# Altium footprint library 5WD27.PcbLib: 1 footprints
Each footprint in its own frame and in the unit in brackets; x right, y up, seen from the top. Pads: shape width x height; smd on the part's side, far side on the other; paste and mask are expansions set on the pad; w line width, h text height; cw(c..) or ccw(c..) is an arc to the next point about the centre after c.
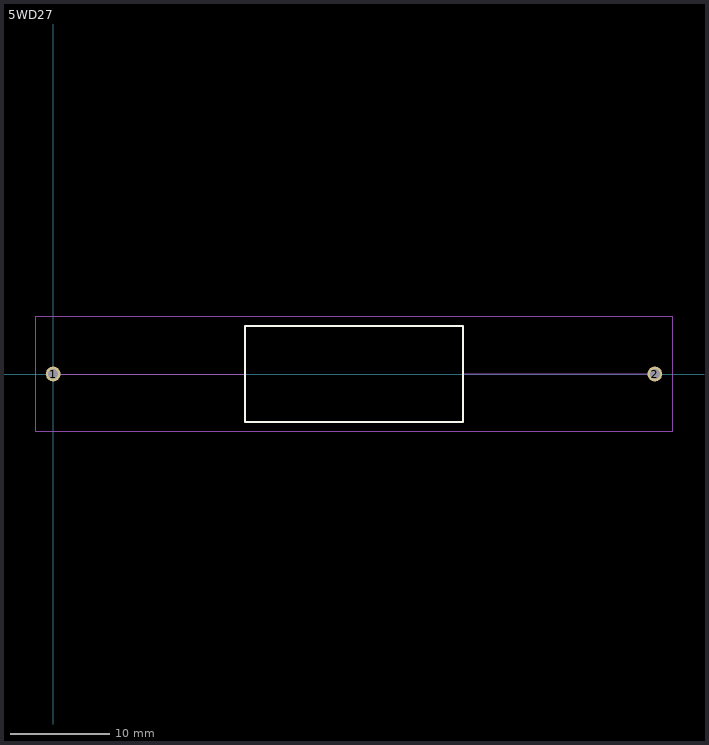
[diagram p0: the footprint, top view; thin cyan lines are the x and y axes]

## 5WD27 [mm]
pads (2):
  round 1.5 hole 1: 1(0,0) 2(60.6,0)
Top Overlay:
  lines w0.2: 19.3,-4.825 41.3,-4.825 41.3,4.825 19.3,4.825 19.3,-4.825
Mechanical 15:
  lines w0.1: 0,0 19.3,0 ; 41.3,0 60.6,0 ; 19.3,-4.825 41.3,-4.825 41.3,4.825 19.3,4.825 19.3,-4.825
Mechanical 20:
  lines w0.1: -1.75,-5.825 62.35,-5.825 62.35,5.825 -1.75,5.825 -1.75,-5.825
